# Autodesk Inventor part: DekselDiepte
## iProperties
Created: 2010-03
Part Number: DekselDiepte
Document SubType Name: Modeling
Designer: Ferry
Density: 1 g/cm^3
Author: Ferry
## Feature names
1. Extrusion1
